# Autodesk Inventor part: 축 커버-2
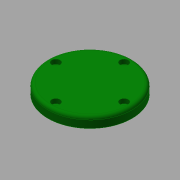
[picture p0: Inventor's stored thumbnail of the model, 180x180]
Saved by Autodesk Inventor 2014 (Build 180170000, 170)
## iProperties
Created: 2015-10
Part Number: 축 커버-2
Document SubType Name: Modeling
Designer: mdu
Density: 1 g/cm^3
Material: 강철, 연강
Appearance: 진녹색
Author: mdu
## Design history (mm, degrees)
sketch "스케치1"
  geometry: C1 r 40 at (0, 0) reference; C2 r 26 at (0, 0) reference; 1 further point
  node "참조1"
  node "참조2"
extrude "돌출1" new body sketch "스케치1" distance "d0" = 10; taper "d1" = 0 deg
extrude "돌출2" join sketch "스케치1" distance "d2" = 3; taper "d3" = 0 deg
sketch "스케치2"
  geometry: C1 r 20 at (0, 0); 1 further point
  constraints: 1 centre point, 1 coincident
  dimensions: "d13" = 40 diameter of C1
extrude "돌출3" cut sketch "스케치2" distance "d14" = 3; taper "d15" = 0 deg
sketch "스케치3"
  geometry: C1 r 1.621 at (0, 32.5) reference; 1 further point
hole "구멍2" sketch "스케치3" at (0, 32.5) diameter "d16" = 4.5; stored, may be unused: countersink angle "d20" = 90 deg, drill point angle "d22" = 118 deg; dims "d17" = 6, "d18" = 8, "d19" = 4.4, "d21" = 8
fillet "모깎기1" dims "d26" = 3, "d27" = 0.3
chamfer "모따기1" distance "d28" = 1; stored, may be unused: second distance "d29" = 2, angle "d30" = 45 deg
node "솔리드1"
pattern_circular "원형 패턴1" dims angle "d24" = 360 deg
node "참조3"
